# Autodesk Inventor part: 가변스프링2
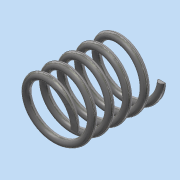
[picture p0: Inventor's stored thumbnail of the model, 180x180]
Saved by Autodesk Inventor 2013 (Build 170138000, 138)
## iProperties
Created: 2018-10
Part Number: 가변스프링2
Material: 스테인리스강
Document SubType Name: Modeling
Designer: Administrator
Density: 8.08 g/cm^3
Mass: 6.26489 g
Surface Area: 15.7543 cm^2
Volume: 0.775357 cm^3
Author: Administrator
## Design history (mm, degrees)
sketch "스케치1"
  geometry: L1 (0, 0)-(0, 24.745); L2 (0, 24.745)-(8, 24.745); L3 (0, 0)-(8, 0); C1 r 1 at (8, 0)
  constraints: 6 end point, 1 centre point, 1 coincident, 1 parallel, 1 perpendicular, 1 vertical
  dimensions: "d0" = 24.74499 distance of L1.start L1.end (derived); "d1" = 8 distance of L1.end L2.end; "d3" = 2 diameter of C1; "d4" = 16 diameter of L3.end L1
feature "코일1" sketch "스케치1" pitch "d5" = 10; turns "d7" = 5; dims "d6" = 24.74499 (= d0), "d8" = 0, angle "d9" = 90 deg, angle "d10" = 90 deg, "d11" = 0, "d12" = 0
sketch "스케치2"
  geometry: L1 (24.745, 10)-(0, 10); L2 (0, 10)-(0, -10); L3 (0, -10)-(24.745, -10); L4 (24.745, -10)-(24.745, 10); 2 further points
  constraints: 8 end point, 2 parallel, 1 coincident, 1 horizontal, 1 midpoint, 1 perpendicular
  dimensions: "d13" = 24.74499 distance of L2.end L3.end (derived); "d15" = 20 distance between parallel lines of L3 L1
extrude "돌출1" sketch "스케치2" stored distance "d16" = 0; taper "d17" = 0 deg
node "솔리드1"
